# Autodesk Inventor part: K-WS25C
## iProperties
Created: 2009-07
Part Number: K-WS25C
Document SubType Name: Modeling
Designer: TB
Mass: 59.0139 g
Surface Area: 152.624 cm^2
Volume: 59.0139 cm^3
Density: 1 g/cm^3
Author: TB
